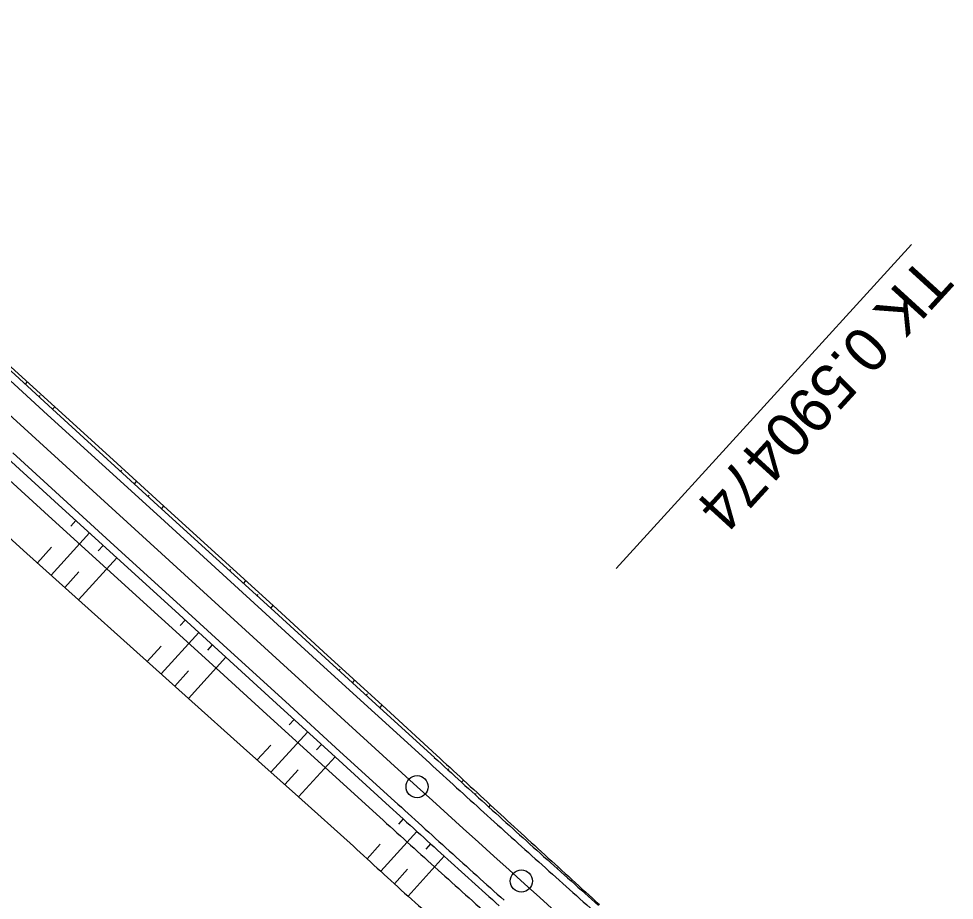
# Model space of a CAD drawing. Extents: x -481645 to -478728, y -1113199 to -1110710.
# Drawn here: x -481324.6 to -481261.3, y -1113006.1 to -1112946.4 of the extents above; entities that cross this region are included whole.
import ezdxf

# ---------------------------------------------------------------- set-up
doc = ezdxf.new("R2010")
doc.units = 0
for name, color, linetype in [('Vrstva 41', 7, 'Continuous'), ('Vrstva 42', 7, 'Continuous'), ('Vrstva 43', 7, 'Continuous'), ('Vrstva 44', 7, 'Continuous'), ('Vrstva 45', 7, 'Continuous'), ('Vrstva 46', 7, 'Continuous'), ('Vrstva 48', 7, 'Continuous'), ('Vrstva 49', 7, 'Continuous'), ('Vrstva 50', 7, 'Continuous'), ('Vrstva 51', 7, 'Continuous')]:
    doc.layers.add(name, color=color, linetype=linetype)

msp = doc.modelspace()

# ---------------------------------------------------------------- linework, layer by layer
at = {"layer": 'Vrstva 41'}
msp.add_line((-481354.685, -1112946.378), (-481297.645, -1112998.401), dxfattribs=at)
msp.add_arc((-480489, -1112111.782), 1200, 227.633469, 229.772919, dxfattribs=at)
at = {"layer": 'Vrstva 42'}
for p, q in [((-481325.886, -1112969.303), (-481322.188, -1112972.668)), ((-481322.188, -1112972.668), (-481318.491, -1112976.034)), ((-481318.491, -1112976.034), (-481314.794, -1112979.401)), ((-481328.022, -1112979.065), (-481324.301, -1112982.404)), ((-481314.794, -1112979.401), (-481311.098, -1112982.768)), ((-481324.301, -1112982.404), (-481320.578, -1112985.742)), ((-481311.098, -1112982.768), (-481307.401, -1112986.135)), ((-481320.578, -1112985.742), (-481316.854, -1112989.08)), ((-481307.401, -1112986.135), (-481303.705, -1112989.502)), ((-481316.854, -1112989.08), (-481313.131, -1112992.417)), ((-481303.705, -1112989.502), (-481300.013, -1112992.874)), ((-481313.131, -1112992.417), (-481309.409, -1112995.756)), ((-481300.013, -1112992.874), (-481296.334, -1112996.259)), ((-481309.409, -1112995.756), (-481305.685, -1112999.092)), ((-481305.685, -1112999.092), (-481301.964, -1113002.433))]:
    msp.add_line(p, q, dxfattribs=at)
for centre, radius, start, end in [((-478855.272, -1110360.177), 3592.73, 227.199736, 227.279331), ((-480481.437, -1112118.658), 1197.598, 227.360553, 227.599294), ((-478858.068, -1110334.99), 3617.717, 227.504256, 227.583797), ((-480481.223, -1112118.795), 1197.641, 227.587328, 227.826069), ((-480504.17, -1112098.337), 1205.863, 228.812678, 229.051444)]:
    msp.add_arc(centre, radius, start, end, dxfattribs=at)
at = {"layer": 'Vrstva 43'}
for p, q in [((-481326.059, -1112976.912), (-481322.361, -1112980.277)), ((-481322.361, -1112980.277), (-481318.663, -1112983.642)), ((-481318.663, -1112983.642), (-481314.964, -1112987.007)), ((-481314.964, -1112987.007), (-481311.266, -1112990.372)), ((-481311.266, -1112990.372), (-481307.568, -1112993.737)), ((-481307.568, -1112993.737), (-481303.87, -1112997.102)), ((-481303.87, -1112997.102), (-481300.172, -1113000.467))]:
    msp.add_line(p, q, dxfattribs=at)
for centre, radius, start, end in [((-478873.53, -1110328.177), 3609.671, 227.758172, 227.837731), ((-480490.048, -1112110.838), 1203.221, 227.916725, 228.155458)]:
    msp.add_arc(centre, radius, start, end, dxfattribs=at)
at = {"layer": 'Vrstva 44'}
for p, q in [((-481326.033, -1112969.464), (-481322.339, -1112972.833)), ((-481322.339, -1112972.833), (-481318.645, -1112976.203)), ((-481325.371, -1112976.158), (-481321.677, -1112979.528)), ((-481318.645, -1112976.203), (-481314.95, -1112979.572)), ((-481321.677, -1112979.528), (-481317.983, -1112982.897)), ((-481314.95, -1112979.572), (-481311.256, -1112982.941)), ((-481317.983, -1112982.897), (-481314.289, -1112986.266)), ((-481311.256, -1112982.941), (-481307.562, -1112986.311)), ((-481314.289, -1112986.266), (-481310.594, -1112989.636)), ((-481307.562, -1112986.311), (-481303.868, -1112989.68)), ((-481310.594, -1112989.636), (-481306.9, -1112993.005)), ((-481303.868, -1112989.68), (-481300.174, -1112993.05)), ((-481306.9, -1112993.005), (-481303.206, -1112996.374)), ((-481300.174, -1112993.05), (-481296.479, -1112996.419)), ((-481303.206, -1112996.374), (-481299.512, -1112999.744))]:
    msp.add_line(p, q, dxfattribs=at)
for centre, radius, start, end in [((-478877.782, -1110339.099), 3593.25, 227.691481, 227.771072), ((-478871.729, -1110332.438), 3606.75, 227.691528, 227.771092), ((-480489, -1112111.782), 1197.75, 227.849589, 228.088322), ((-480489, -1112111.782), 1202.25, 227.849589, 228.088322), ((-480489, -1112111.782), 1197.75, 228.088322, 228.327056)]:
    msp.add_arc(centre, radius, start, end, dxfattribs=at)
at = {"layer": 'Vrstva 45'}
for p, q in [((-481326.37, -1112969.833), (-481322.676, -1112973.203)), ((-481322.676, -1112973.203), (-481318.982, -1112976.572)), ((-481325.034, -1112975.789), (-481321.34, -1112979.158)), ((-481318.982, -1112976.572), (-481315.287, -1112979.942)), ((-481321.34, -1112979.158), (-481317.646, -1112982.528)), ((-481315.287, -1112979.942), (-481311.593, -1112983.311)), ((-481317.646, -1112982.528), (-481313.952, -1112985.897)), ((-481311.593, -1112983.311), (-481307.899, -1112986.68)), ((-481313.952, -1112985.897), (-481310.257, -1112989.266)), ((-481307.899, -1112986.68), (-481304.205, -1112990.05)), ((-481310.257, -1112989.266), (-481306.563, -1112992.636)), ((-481304.205, -1112990.05), (-481300.51, -1112993.419)), ((-481306.563, -1112992.636), (-481302.869, -1112996.005)), ((-481300.51, -1112993.419), (-481296.816, -1112996.788)), ((-481302.869, -1112996.005), (-481299.175, -1112999.374))]:
    msp.add_line(p, q, dxfattribs=at)
for centre, radius, start, end in [((-478877.109, -1110338.359), 3594.75, 227.691486, 227.771075), ((-478872.402, -1110333.178), 3605.25, 227.691525, 227.771092), ((-480489, -1112111.782), 1198.25, 227.849589, 228.088322), ((-480489, -1112111.782), 1201.75, 227.849589, 228.088322), ((-480489, -1112111.782), 1198.25, 228.088322, 228.327056)]:
    msp.add_arc(centre, radius, start, end, dxfattribs=at)
at = {"layer": 'Vrstva 46'}
for p, q in [((-481326.37, -1112969.833), (-481322.676, -1112973.203)), ((-481322.676, -1112973.203), (-481318.982, -1112976.572)), ((-481325.034, -1112975.789), (-481321.34, -1112979.158)), ((-481318.982, -1112976.572), (-481315.287, -1112979.942)), ((-481321.34, -1112979.158), (-481317.646, -1112982.528)), ((-481315.287, -1112979.942), (-481311.593, -1112983.311)), ((-481317.646, -1112982.528), (-481313.952, -1112985.897)), ((-481311.593, -1112983.311), (-481307.899, -1112986.68)), ((-481313.952, -1112985.897), (-481310.257, -1112989.266)), ((-481307.899, -1112986.68), (-481304.205, -1112990.05)), ((-481310.257, -1112989.266), (-481306.563, -1112992.636)), ((-481304.205, -1112990.05), (-481300.51, -1112993.419)), ((-481306.563, -1112992.636), (-481302.869, -1112996.005)), ((-481300.51, -1112993.419), (-481296.816, -1112996.788)), ((-481302.869, -1112996.005), (-481299.175, -1112999.374))]:
    msp.add_line(p, q, dxfattribs=at)
for centre, radius, start, end in [((-478877.109, -1110338.359), 3594.75, 227.691486, 227.771075), ((-478872.402, -1110333.178), 3605.25, 227.691525, 227.771092), ((-480489, -1112111.782), 1198.25, 227.849589, 228.088322), ((-480489, -1112111.782), 1201.75, 227.849589, 228.088322), ((-480489, -1112111.782), 1198.25, 228.088322, 228.327056)]:
    msp.add_arc(centre, radius, start, end, dxfattribs=at)
at = {"layer": 'Vrstva 48'}
msp.add_line((-481264.154, -1112961.68), (-481284.168, -1112983.624), dxfattribs=at)
msp.add_circle((-481297.645, -1112998.401), 0.75, dxfattribs=at)
at = {"layer": 'Vrstva 49'}
msp.add_circle((-481290.582, -1113004.792), 0.75, dxfattribs=at)
at = {"layer": 'Vrstva 50'}
for p, q in [((-481324.186, -1112971.149), (-481324.037, -1112970.985)), ((-481323.263, -1112971.991), (-481323.188, -1112971.908)), ((-481323.112, -1112971.826), (-481323.112, -1112971.826)), ((-481322.339, -1112972.833), (-481322.188, -1112972.668)), ((-481317.721, -1112977.045), (-481317.644, -1112976.96)), ((-481317.567, -1112976.876), (-481317.567, -1112976.876)), ((-481316.798, -1112977.887), (-481316.643, -1112977.717)), ((-481315.874, -1112978.73), (-481315.796, -1112978.644)), ((-481315.718, -1112978.559), (-481315.718, -1112978.559)), ((-481314.95, -1112979.572), (-481314.794, -1112979.401)), ((-481310.333, -1112983.784), (-481310.254, -1112983.697)), ((-481310.174, -1112983.61), (-481310.174, -1112983.61)), ((-481309.409, -1112984.626), (-481309.25, -1112984.451)), ((-481308.486, -1112985.468), (-481308.406, -1112985.38)), ((-481308.325, -1112985.293), (-481308.325, -1112985.293)), ((-481307.562, -1112986.311), (-481307.401, -1112986.135)), ((-481302.944, -1112990.522), (-481302.863, -1112990.434)), ((-481302.782, -1112990.345), (-481302.782, -1112990.345)), ((-481302.021, -1112991.365), (-481301.859, -1112991.188)), ((-481301.097, -1112992.207), (-481301.017, -1112992.119)), ((-481300.936, -1112992.031), (-481300.936, -1112992.031)), ((-481300.174, -1112993.05), (-481300.013, -1112992.874)), ((-481295.557, -1112997.26), (-481295.487, -1112997.184)), ((-481295.418, -1112997.108), (-481295.418, -1112997.108)), ((-481294.634, -1112998.1), (-481294.503, -1112997.956)), ((-481293.71, -1112998.938), (-481293.648, -1112998.87)), ((-481293.586, -1112998.802), (-481293.586, -1112998.802)), ((-481292.786, -1112999.776), (-481292.669, -1112999.648)), ((-481288.15, -1113003.951), (-481288.11, -1113003.906)), ((-481288.07, -1113003.861), (-481288.07, -1113003.861)), ((-481287.22, -1113004.782), (-481287.147, -1113004.701)), ((-481286.289, -1113005.613), (-481286.256, -1113005.576)), ((-481286.224, -1113005.54), (-481286.224, -1113005.54))]:
    msp.add_line(p, q, dxfattribs=at)
at = {"layer": 'Vrstva 51'}
for p, q in [((-481320.754, -1112980.37), (-481321.095, -1112980.744)), ((-481319.83, -1112981.212), (-481322.439, -1112984.073)), ((-481322.403, -1112982.178), (-481323.37, -1112983.238)), ((-481318.906, -1112982.055), (-481319.246, -1112982.428)), ((-481317.983, -1112982.897), (-481320.578, -1112985.742)), ((-481320.548, -1112983.854), (-481321.508, -1112984.907)), ((-481313.365, -1112987.109), (-481313.702, -1112987.479)), ((-481312.442, -1112987.951), (-481314.993, -1112990.748)), ((-481314.982, -1112988.882), (-481315.924, -1112989.914)), ((-481311.518, -1112988.793), (-481311.854, -1112989.162)), ((-481310.594, -1112989.636), (-481313.131, -1112992.417)), ((-481313.126, -1112990.557), (-481314.062, -1112991.583)), ((-481305.977, -1112993.847), (-481306.311, -1112994.213)), ((-481305.053, -1112994.69), (-481307.547, -1112997.424)), ((-481304.129, -1112995.532), (-481304.462, -1112995.896)), ((-481307.561, -1112995.584), (-481308.478, -1112996.59)), ((-481303.206, -1112996.374), (-481305.685, -1112999.092)), ((-481305.706, -1112997.26), (-481306.616, -1112998.258)), ((-481298.587, -1113000.587), (-481298.917, -1113000.948)), ((-481297.661, -1113001.43), (-481300.114, -1113004.129)), ((-481300.143, -1113002.295), (-481301.04, -1113003.28)), ((-481296.733, -1113002.272), (-481297.061, -1113002.633)), ((-481295.805, -1113003.112), (-481298.259, -1113005.823)), ((-481298.288, -1113003.985), (-481299.187, -1113004.976))]:
    msp.add_line(p, q, dxfattribs=at)

# ---------------------------------------------------------------- texts
at = {"layer": 'Vrstva 48'}
msp.add_text('TK 0.590474', height=2.999, rotation=227.63348, dxfattribs=at).set_placement((-481263.415, -1112962.353))

doc.saveas('drawing.dxf')
